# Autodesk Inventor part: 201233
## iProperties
Created: 2007-12
Part Number: 201233
Document SubType Name: Modeling
Designer: MM
Density: 7.85 g/cm^3
Mass: 1039.32 g
Surface Area: 1235.29 cm^2
Volume: 132.397 cm^3
Material: Steel
Description: TOP LEFT SIDE PLATE
Component Category: Lower Component
Author: MM
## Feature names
1. TaggingFeature2
